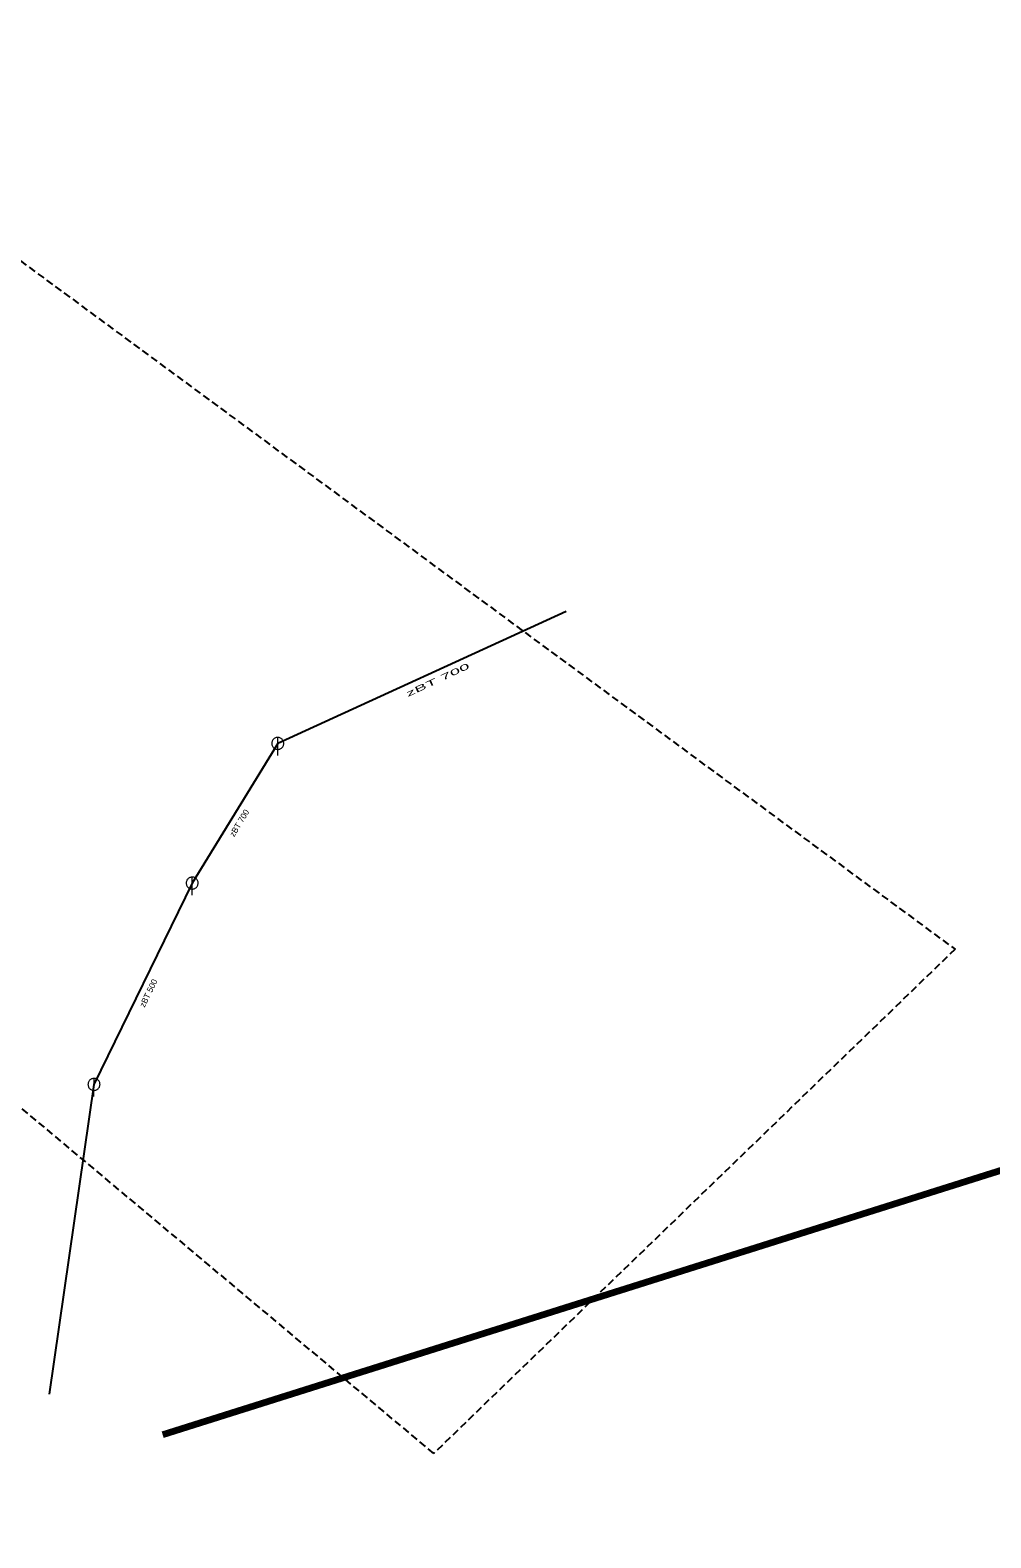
# Model space of a CAD drawing. Extents: x -687195 to -686201, y -974149 to -973877.
# Drawn here: x -687038.1 to -686878.1, y -974149.2 to -973898 of the extents above; entities that cross this region are included whole.
import ezdxf

# ---------------------------------------------------------------- set-up
doc = ezdxf.new("R2010")
doc.units = 0
doc.header["$LTSCALE"] = 0.4
doc.linetypes.add('MEDIUM_DASHED', pattern=[4.5, 3, -1.5])
doc.layers.add('1', color=7, linetype='Continuous')
for name, color, linetype, lineweight in [('14', 7, 'Continuous', 25), ('22', 7, 'Continuous', 13), ('27', 7, 'Continuous', 158), ('63', 7, 'MEDIUM_DASHED', 25)]:
    doc.layers.add(name, color=color, linetype=linetype, lineweight=lineweight)

msp = doc.modelspace()

# ---------------------------------------------------------------- linework, layer by layer
at = {"layer": '14'}
for p, q in [((-686948.853, -973994.916), (-686996.895, -974016.874)), ((-686609.228, -974003.734), (-687016.03, -974132.098)), ((-686996.895, -974016.874), (-687011.146, -974040.155)), ((-687011.146, -974040.155), (-687027.498, -974073.704)), ((-687027.498, -974073.704), (-687034.957, -974125.306))]:
    msp.add_line(p, q, dxfattribs=at)
at = {"layer": '22'}
for p, q in [((-686996.895, -974018.874), (-686996.894, -974015.874)), ((-687011.146, -974042.155), (-687011.145, -974039.155)), ((-687027.498, -974075.704), (-687027.497, -974072.704))]:
    msp.add_line(p, q, dxfattribs=at)
for points in [[(-686995.895, -974016.874), (-686995.9, -974016.765), (-686995.918, -974016.657), (-686995.948, -974016.551), (-686995.988, -974016.45), (-686996.04, -974016.353), (-686996.102, -974016.263), (-686996.174, -974016.18), (-686996.254, -974016.106), (-686996.342, -974016.04), (-686996.436, -974015.985), (-686996.536, -974015.94), (-686996.641, -974015.907), (-686996.748, -974015.885), (-686996.857, -974015.875), (-686996.967, -974015.877), (-686997.075, -974015.891), (-686997.182, -974015.916), (-686997.285, -974015.953), (-686997.383, -974016.002), (-686997.475, -974016.06), (-686997.561, -974016.129), (-686997.638, -974016.206), (-686997.707, -974016.292), (-686997.766, -974016.384), (-686997.814, -974016.482), (-686997.851, -974016.585), (-686997.877, -974016.692), (-686997.891, -974016.8), (-686997.894, -974016.91), (-686997.884, -974017.019), (-686997.863, -974017.126), (-686997.829, -974017.23), (-686997.785, -974017.33), (-686997.73, -974017.425), (-686997.664, -974017.513), (-686997.59, -974017.593), (-686997.507, -974017.665), (-686997.417, -974017.727), (-686997.321, -974017.779), (-686997.219, -974017.82), (-686997.114, -974017.85), (-686997.006, -974017.868), (-686996.896, -974017.874), (-686996.787, -974017.868), (-686996.679, -974017.85), (-686996.574, -974017.821), (-686996.472, -974017.78), (-686996.375, -974017.728), (-686996.285, -974017.666), (-686996.202, -974017.595), (-686996.127, -974017.515), (-686996.062, -974017.427), (-686996.006, -974017.333), (-686995.962, -974017.233), (-686995.928, -974017.129), (-686995.906, -974017.021), (-686995.896, -974016.912)], [(-687010.146, -974040.155), (-687010.151, -974040.046), (-687010.169, -974039.938), (-687010.199, -974039.832), (-687010.239, -974039.731), (-687010.291, -974039.634), (-687010.353, -974039.544), (-687010.425, -974039.461), (-687010.505, -974039.387), (-687010.593, -974039.321), (-687010.687, -974039.266), (-687010.787, -974039.221), (-687010.892, -974039.188), (-687010.999, -974039.166), (-687011.108, -974039.156), (-687011.218, -974039.158), (-687011.326, -974039.172), (-687011.433, -974039.197), (-687011.536, -974039.234), (-687011.634, -974039.283), (-687011.726, -974039.341), (-687011.812, -974039.41), (-687011.889, -974039.487), (-687011.958, -974039.573), (-687012.017, -974039.665), (-687012.065, -974039.763), (-687012.102, -974039.866), (-687012.128, -974039.973), (-687012.142, -974040.081), (-687012.145, -974040.191), (-687012.135, -974040.3), (-687012.114, -974040.407), (-687012.08, -974040.511), (-687012.036, -974040.611), (-687011.981, -974040.706), (-687011.915, -974040.794), (-687011.841, -974040.874), (-687011.758, -974040.946), (-687011.668, -974041.008), (-687011.572, -974041.06), (-687011.47, -974041.101), (-687011.365, -974041.131), (-687011.257, -974041.149), (-687011.147, -974041.155), (-687011.038, -974041.149), (-687010.93, -974041.131), (-687010.825, -974041.102), (-687010.723, -974041.061), (-687010.626, -974041.009), (-687010.536, -974040.947), (-687010.453, -974040.876), (-687010.378, -974040.796), (-687010.313, -974040.708), (-687010.257, -974040.614), (-687010.213, -974040.514), (-687010.179, -974040.41), (-687010.157, -974040.302), (-687010.147, -974040.193)], [(-687026.498, -974073.704), (-687026.503, -974073.595), (-687026.521, -974073.487), (-687026.551, -974073.381), (-687026.591, -974073.28), (-687026.643, -974073.183), (-687026.705, -974073.093), (-687026.777, -974073.01), (-687026.857, -974072.936), (-687026.945, -974072.87), (-687027.039, -974072.815), (-687027.139, -974072.77), (-687027.244, -974072.737), (-687027.351, -974072.715), (-687027.46, -974072.705), (-687027.57, -974072.707), (-687027.678, -974072.721), (-687027.785, -974072.746), (-687027.888, -974072.783), (-687027.986, -974072.832), (-687028.078, -974072.89), (-687028.164, -974072.959), (-687028.241, -974073.036), (-687028.31, -974073.122), (-687028.369, -974073.214), (-687028.417, -974073.312), (-687028.454, -974073.415), (-687028.48, -974073.522), (-687028.494, -974073.63), (-687028.497, -974073.74), (-687028.487, -974073.849), (-687028.466, -974073.956), (-687028.432, -974074.06), (-687028.388, -974074.16), (-687028.333, -974074.255), (-687028.267, -974074.343), (-687028.193, -974074.423), (-687028.11, -974074.495), (-687028.02, -974074.557), (-687027.924, -974074.609), (-687027.822, -974074.65), (-687027.717, -974074.68), (-687027.609, -974074.698), (-687027.499, -974074.704), (-687027.39, -974074.698), (-687027.282, -974074.68), (-687027.177, -974074.651), (-687027.075, -974074.61), (-687026.978, -974074.558), (-687026.888, -974074.496), (-687026.805, -974074.425), (-687026.73, -974074.345), (-687026.665, -974074.257), (-687026.609, -974074.163), (-687026.565, -974074.063), (-687026.531, -974073.959), (-687026.509, -974073.851), (-687026.499, -974073.742)]]:
    msp.add_lwpolyline(points, close=True, dxfattribs=at)
at = {"layer": '27'}
msp.add_lwpolyline([(-686201.138, -973955.681), (-686609.228, -974003.734), (-687016.03, -974132.098)], dxfattribs=at)
msp.add_lwpolyline([(-686201.138, -973955.681), (-686609.228, -974003.734), (-687016.03, -974132.098)], dxfattribs=at)
at = {"layer": '63'}
msp.add_lwpolyline([(-687195.201, -974006.159), (-687144.96, -973932.203), (-687144.96, -973932.203), (-687091.904, -973898.039), (-687091.904, -973898.039), (-686884.104, -974051.176), (-686884.104, -974051.176), (-686970.922, -974135.181), (-686970.922, -974135.181), (-687042.868, -974074.89), (-687042.868, -974074.89), (-687130.088, -974149.248), (-687130.088, -974149.248), (-687180.33, -974098.203), (-687180.33, -974098.203), (-687127.274, -974033.491), (-687127.274, -974033.491)], close=True, dxfattribs=at)

# ---------------------------------------------------------------- texts
at = {"layer": '1', "width": 2.3}
msp.add_text('zBT 700 ', height=1, rotation=25, dxfattribs=at).set_placement((-686975.232, -974009.155))
at = {"layer": '1'}
for s, rotation, p in [('zBT 700 ', 59, (-687004.154, -974032.536)), ('zBT 500 ', 64, (-687019.07, -974060.946))]:
    msp.add_text(s, height=1, rotation=rotation, dxfattribs=at).set_placement(p)

doc.saveas('drawing.dxf')
